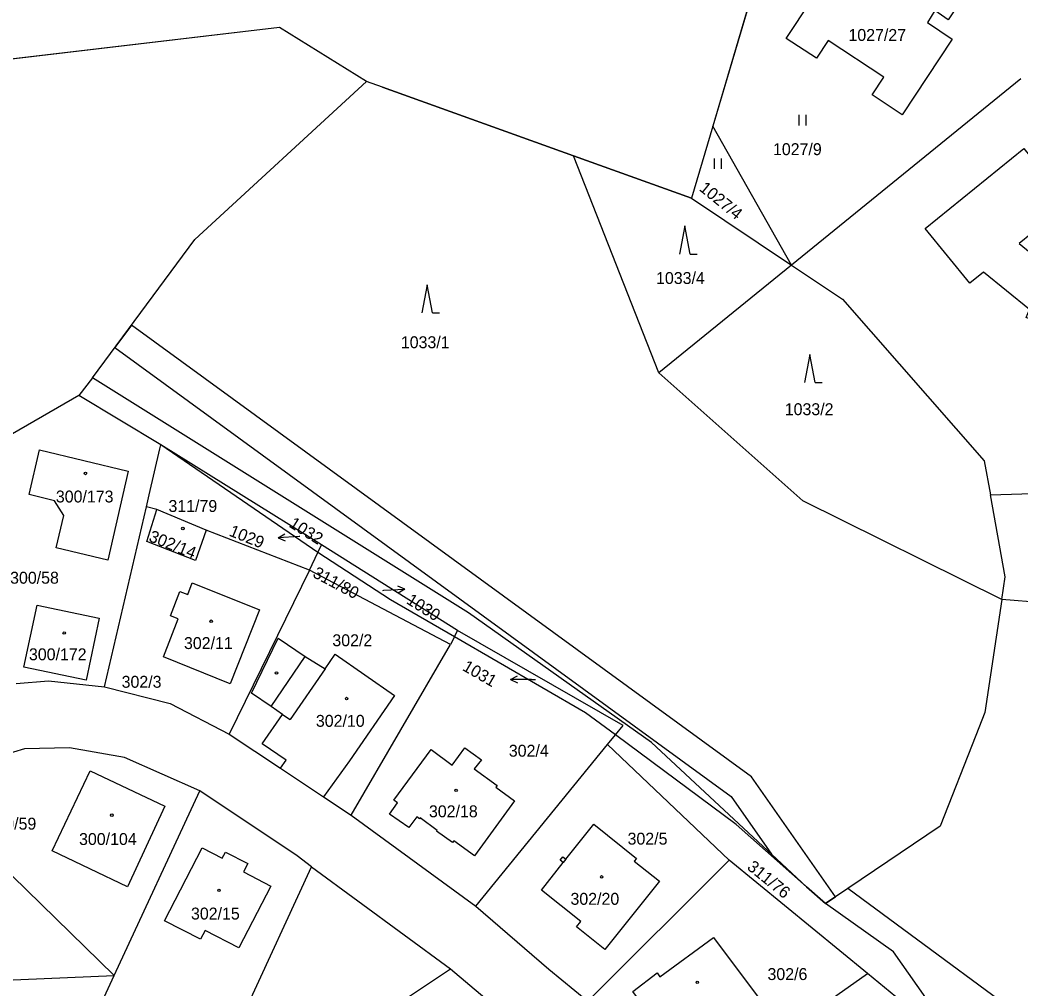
# Model space of a CAD drawing. Extents: x -757266 to -753360, y -1162585 to -1157740.
# Drawn here: x -754707.7 to -754565.1, y -1160582.8 to -1160444.8 of the extents above; entities that cross this region are included whole.
import ezdxf

# ---------------------------------------------------------------- set-up
doc = ezdxf.new("R2010")
doc.units = 0
for name, color, linetype in [('Hranice kat_území', 7, 'Continuous'), ('Hranice parcel', 7, 'Continuous'), ('Parcelní čísla', 7, 'Continuous'), ('Pop  PČ popisy', 7, 'Continuous'), ('Vnitřní kresba', 7, 'Continuous'), ('Věcná břemena k části', 7, 'Continuous'), ('Značky budov', 7, 'Continuous'), ('Značky kultur', 7, 'Continuous')]:
    doc.layers.add(name, color=color, linetype=linetype)

msp = doc.modelspace()

# ---------------------------------------------------------------- linework, layer by layer
at = {"layer": 'Hranice kat_území'}
msp.add_lwpolyline([(-754561.41, -1160428.29), (-754599.4, -1160427.7), (-754608.96, -1160459.95), (-754612, -1160470.2), (-754628.81, -1160464.16), (-754656.06, -1160454.38), (-754658.34, -1160453.56), (-754670.71, -1160445.87), (-754748.18, -1160454.98), (-754763.13, -1160445.62), (-754770.6, -1160434.89), (-754825.24, -1160422.53), (-754831.13, -1160423.76), (-754836.68, -1160424.92)], dxfattribs=at)
at = {"layer": 'Hranice parcel'}
for p, q in [((-754599.4, -1160427.7), (-754608.96, -1160459.95)), ((-754670.71, -1160445.87), (-754748.18, -1160454.98)), ((-754658.34, -1160453.56), (-754670.71, -1160445.87)), ((-754656.06, -1160454.38), (-754658.34, -1160453.56)), ((-754565.04, -1160453.21), (-754597.74, -1160479.74)), ((-754656.06, -1160454.38), (-754628.81, -1160464.16)), ((-754608.96, -1160459.95), (-754612, -1160470.2)), ((-754597.74, -1160479.74), (-754608.96, -1160459.95)), ((-754628.81, -1160464.16), (-754612, -1160470.2)), ((-754616.64, -1160495.12), (-754628.81, -1160464.16)), ((-754612, -1160470.2), (-754597.74, -1160479.74)), ((-754597.74, -1160479.74), (-754616.64, -1160495.12)), ((-754697.37, -1160495.81), (-754699.35, -1160498.35)), ((-754699.35, -1160498.35), (-754718.28, -1160509.25)), ((-754687.64, -1160505.4), (-754699.35, -1160498.35)), ((-754665.25, -1160520.72), (-754687.64, -1160505.4)), ((-754664.73, -1160519.64), (-754687.64, -1160505.4)), ((-754569.37, -1160512.49), (-754528.72, -1160511.17)), ((-754695.7, -1160539.88), (-754689.68, -1160514.2)), ((-754688.24, -1160514.59), (-754689.68, -1160514.2)), ((-754681.17, -1160517.53), (-754688.24, -1160514.59)), ((-754666.47, -1160523.27), (-754681.17, -1160517.53)), ((-754665.25, -1160520.72), (-754664.73, -1160519.64)), ((-754645.36, -1160531.87), (-754664.73, -1160519.64)), ((-754666.47, -1160523.27), (-754665.25, -1160520.72)), ((-754666.47, -1160523.27), (-754677.92, -1160546.62)), ((-754646.33, -1160533.85), (-754666.47, -1160523.27)), ((-754550.24, -1160528.86), (-754567.75, -1160527.45)), ((-754645.8, -1160532.77), (-754645.36, -1160531.87)), ((-754645.8, -1160532.77), (-754646.33, -1160533.85)), ((-754660.51, -1160558.19), (-754646.33, -1160533.85)), ((-754677.92, -1160546.62), (-754670.6, -1160551.49)), ((-754623.96, -1160548.12), (-754622.84, -1160546.75)), ((-754642.73, -1160571.16), (-754623.96, -1160548.12)), ((-754606.61, -1160564.59), (-754623.96, -1160548.12)), ((-754670.6, -1160551.49), (-754664.45, -1160555.57)), ((-754694.29, -1160581.04), (-754682.09, -1160554.71)), ((-754720.47, -1160555.5), (-754694.29, -1160581.04)), ((-754664.45, -1160555.57), (-754660.51, -1160558.19)), ((-754660.51, -1160558.19), (-754642.73, -1160571.16)), ((-754626.77, -1160584.73), (-754606.61, -1160564.59)), ((-754586.88, -1160580.76), (-754606.61, -1160564.59)), ((-754677.4, -1160589.9), (-754666.17, -1160565.55)), ((-754666.17, -1160565.55), (-754646.35, -1160580.1)), ((-754592.9, -1160570.8), (-754595.57, -1160568.42)), ((-754589.68, -1160568.64), (-754592.9, -1160570.8)), ((-754670.52, -1160596.18), (-754646.35, -1160580.1)), ((-754729.14, -1160582.6), (-754694.29, -1160581.04)), ((-754696.01, -1160584.78), (-754694.29, -1160581.04)), ((-754573.05, -1160592.1), (-754586.88, -1160580.76))]:
    msp.add_line(p, q, dxfattribs=at)
for points in [[(-754580.41, -1160431.85), (-754570.99, -1160438.07), (-754575.39, -1160444.75), (-754577.29, -1160443.45), (-754578.34, -1160445.15), (-754574.81, -1160447.52), (-754581.93, -1160458.3), (-754586.23, -1160455.47), (-754584.57, -1160452.94), (-754592.51, -1160447.73), (-754594.17, -1160450.25), (-754598.47, -1160447.42), (-754591.34, -1160436.64), (-754585.8, -1160440.24), (-754580.41, -1160431.85)], [(-754697.37, -1160495.81), (-754682.82, -1160476.1), (-754658.34, -1160453.56)], [(-754551.18, -1160493.01), (-754551.92, -1160494.72), (-754562.62, -1160489.98), (-754561.86, -1160488.29), (-754564.28, -1160487.21), (-754563.77, -1160486.1), (-754570.33, -1160480.78), (-754572.3, -1160482.34), (-754578.65, -1160474.52), (-754564.61, -1160463.11), (-754558.25, -1160470.95), (-754565.26, -1160476.67), (-754561.08, -1160480.09), (-754559.99, -1160477.51), (-754541.63, -1160485.62), (-754545.9, -1160495.32), (-754551.18, -1160493.01)], [(-754597.74, -1160479.74), (-754590.44, -1160484.62), (-754570.24, -1160507.65), (-754569.37, -1160512.49)], [(-754595.57, -1160568.42), (-754617.69, -1160547.83), (-754643.8, -1160529.32), (-754697.37, -1160495.81)], [(-754567.75, -1160527.45), (-754596.13, -1160513.36), (-754616.64, -1160495.12)], [(-754701.5, -1160515.46), (-754702.79, -1160513.35), (-754706.43, -1160512.48), (-754704.93, -1160506.11), (-754692.29, -1160509.15), (-754695.23, -1160521.83), (-754702.56, -1160520.07), (-754701.5, -1160515.46)], [(-754689.68, -1160514.2), (-754689.29, -1160512.5), (-754687.77, -1160505.95), (-754687.64, -1160505.4)], [(-754567.75, -1160527.45), (-754567.27, -1160524.22), (-754569.37, -1160512.49)], [(-754681.17, -1160517.53), (-754682.73, -1160521.87), (-754689.65, -1160519.16), (-754688.24, -1160514.59)], [(-754645.8, -1160532.77), (-754654.9, -1160527.5), (-754665.25, -1160520.72)], [(-754683.82, -1160526.7), (-754683.19, -1160525.08), (-754673.56, -1160528.91), (-754677.76, -1160539.46), (-754687.29, -1160535.63), (-754685.18, -1160530.21), (-754686.29, -1160529.77), (-754684.93, -1160526.27), (-754683.82, -1160526.7)], [(-754567.75, -1160527.45), (-754570.15, -1160543.54), (-754571.44, -1160546.84), (-754576.51, -1160559.77), (-754589.68, -1160568.64)], [(-754707.16, -1160537.08), (-754705.3, -1160528.23), (-754696.46, -1160530.11), (-754698.31, -1160538.96), (-754707.16, -1160537.08)], [(-754622.84, -1160546.75), (-754621.75, -1160545.41), (-754645.36, -1160531.87)], [(-754670.6, -1160551.49), (-754669.8, -1160550.34), (-754673.22, -1160548.02), (-754670.29, -1160543.82), (-754671.91, -1160542.71), (-754674.74, -1160540.77), (-754670.9, -1160532.95), (-754667.08, -1160535.57), (-754664.21, -1160537.3), (-754662.8, -1160535.24), (-754654.31, -1160541.11), (-754660.76, -1160550.44), (-754664.45, -1160555.57)], [(-754622.84, -1160546.75), (-754627.1, -1160543.6), (-754645.8, -1160532.77)], [(-754708.3, -1160539.4), (-754703.69, -1160539.02), (-754695.7, -1160539.88)], [(-754695.7, -1160539.88), (-754686.34, -1160542.25), (-754677.92, -1160546.62)], [(-754595.57, -1160568.42), (-754605.6, -1160559.5), (-754622.84, -1160546.75)], [(-754682.09, -1160554.71), (-754692.82, -1160549.97), (-754700.68, -1160548.61), (-754707.08, -1160548.74), (-754713.39, -1160550.62), (-754720.47, -1160555.5)], [(-754649.12, -1160548.84), (-754646.1, -1160551.05), (-754644.29, -1160548.58), (-754641.95, -1160550.29), (-754642.98, -1160551.59), (-754639.71, -1160553.95), (-754639.89, -1160554.19), (-754637.22, -1160556.13), (-754642.93, -1160564.01), (-754645.89, -1160561.86), (-754646.06, -1160562.1), (-754648.32, -1160560.48), (-754648.23, -1160560.36), (-754650.66, -1160558.59), (-754650.75, -1160558.72), (-754651.17, -1160558.41), (-754652.29, -1160559.96), (-754655.06, -1160558.03), (-754653.91, -1160556.44), (-754654.41, -1160556.07), (-754649.12, -1160548.84)], [(-754692.42, -1160568.43), (-754703.15, -1160563.29), (-754697.73, -1160551.88), (-754687.07, -1160556.9), (-754692.42, -1160568.43)], [(-754666.17, -1160565.55), (-754668.23, -1160564.01), (-754682.09, -1160554.71)], [(-754627.77, -1160573.33), (-754633.38, -1160568.87), (-754630.27, -1160564.95), (-754630.7, -1160564.61), (-754630.33, -1160564.14), (-754629.9, -1160564.48), (-754625.91, -1160559.47), (-754619.83, -1160564.35), (-754620.14, -1160564.74), (-754616.56, -1160567.61), (-754624.34, -1160577.34), (-754628.39, -1160574.12), (-754627.77, -1160573.33)], [(-754687.15, -1160573.26), (-754681.74, -1160562.85), (-754678.9, -1160564.34), (-754678.43, -1160563.45), (-754675.26, -1160565.1), (-754675.87, -1160566.29), (-754671.95, -1160568.32), (-754676.55, -1160577.1), (-754681.35, -1160574.65), (-754681.98, -1160575.86), (-754687.15, -1160573.26)], [(-754525.57, -1160600.85), (-754530.19, -1160600.86), (-754557.24, -1160592.58), (-754589.68, -1160568.64)], [(-754642.73, -1160571.16), (-754632.34, -1160580.17), (-754626.77, -1160584.73)], [(-754573.05, -1160592.1), (-754583.17, -1160577.68), (-754592.9, -1160570.8)], [(-754608.87, -1160575.61), (-754602.05, -1160584.69), (-754606.25, -1160587.9), (-754607.41, -1160586.32), (-754614.29, -1160591.54), (-754620.36, -1160583.31), (-754616.9, -1160580.69), (-754616.48, -1160581.25), (-754608.87, -1160575.61)], [(-754646.35, -1160580.1), (-754633.8, -1160590.71), (-754632.57, -1160592.31)], [(-754614.24, -1160600.29), (-754591.25, -1160583.88), (-754586.88, -1160580.76)]]:
    msp.add_lwpolyline(points, dxfattribs=at)
at = {"layer": 'Pop  PČ popisy'}
for p, q in [((-754670.937, -1160518.617), (-754669.963, -1160518.065)), ((-754667.94, -1160518.46), (-754670.937, -1160518.617)), ((-754670.937, -1160518.617), (-754669.911, -1160519.065)), ((-754667.84, -1160518.45), (-754667.94, -1160518.46)), ((-754656, -1160526.13), (-754655.84, -1160526.12)), ((-754655.84, -1160526.12), (-754652.843, -1160525.963)), ((-754652.843, -1160525.963), (-754653.869, -1160525.515)), ((-754652.843, -1160525.963), (-754653.817, -1160526.515)), ((-754637.811, -1160538.84), (-754636.81, -1160538.339)), ((-754634.81, -1160538.84), (-754637.811, -1160538.84)), ((-754637.811, -1160538.84), (-754636.81, -1160539.341)), ((-754634.81, -1160538.84), (-754634.22, -1160538.84))]:
    msp.add_line(p, q, dxfattribs=at)
at = {"layer": 'Vnitřní kresba'}
for p, q in [((-754671.91, -1160542.71), (-754667.08, -1160535.57)), ((-754664.21, -1160537.3), (-754669.2, -1160544.57)), ((-754670.29, -1160543.82), (-754669.2, -1160544.57)), ((-754629.9, -1160564.48), (-754630.27, -1160564.95))]:
    msp.add_line(p, q, dxfattribs=at)
at = {"layer": 'Věcná břemena k části'}
msp.add_lwpolyline([(-754691.82, -1160488.3), (-754694.2, -1160491.51), (-754606.33, -1160555.55), (-754600.57, -1160563.77), (-754595.57, -1160568.42), (-754592.9, -1160570.8), (-754591.44, -1160569.82), (-754603.43, -1160552.71)], close=True, dxfattribs=at)
at = {"layer": 'Značky budov'}
for centre in [(-754698.3968, -1160509.4592), (-754684.5068, -1160517.3092), (-754680.4768, -1160530.5292), (-754701.4268, -1160532.1992), (-754671.1568, -1160537.9092), (-754661.1568, -1160541.5592), (-754645.5468, -1160554.6392), (-754694.6368, -1160558.1892), (-754624.7968, -1160566.9892), (-754679.3668, -1160568.9192), (-754611.1568, -1160582.0392)]:
    msp.add_circle(centre, 0.175, dxfattribs=at)
at = {"layer": 'Značky kultur'}
for p, q in [((-754596.631, -1160459.84), (-754596.631, -1160458.34)), ((-754595.63, -1160459.84), (-754595.63, -1160458.34)), ((-754608.691, -1160466.04), (-754608.691, -1160464.54)), ((-754607.69, -1160466.04), (-754607.69, -1160464.54)), ((-754612.93, -1160474.17), (-754613.68, -1160478.17)), ((-754612.18, -1160478.17), (-754612.93, -1160474.17)), ((-754612.18, -1160478.17), (-754611.184, -1160478.17)), ((-754649.68, -1160482.55), (-754650.43, -1160486.55)), ((-754648.93, -1160486.55), (-754649.68, -1160482.55)), ((-754648.93, -1160486.55), (-754647.934, -1160486.55)), ((-754595.12, -1160492.48), (-754595.87, -1160496.48)), ((-754594.37, -1160496.48), (-754595.12, -1160492.48)), ((-754594.37, -1160496.48), (-754593.374, -1160496.48))]:
    msp.add_line(p, q, dxfattribs=at)

# ---------------------------------------------------------------- texts
at = {"layer": 'Parcelní čísla'}
for s, p in [('1027/27', (-754589.606, -1160447.78)), ('1027/9', (-754600.367, -1160464.07)), ('1033/4', (-754617.037, -1160482.44)), ('1033/1', (-754653.427, -1160491.6)), ('1033/2', (-754598.687, -1160501.15)), ('300/173', (-754702.616, -1160513.6)), ('311/79', (-754686.56, -1160514.95)), ('300/58', (-754709.14, -1160525.18)), ('302/11', (-754684.35, -1160534.5)), ('302/2', (-754663.19, -1160534.1)), ('300/172', (-754706.456, -1160536.1)), ('302/3', (-754693.24, -1160540.02)), ('302/10', (-754665.54, -1160545.59)), ('302/4', (-754638.03, -1160549.85)), ('302/18', (-754649.42, -1160558.49)), ('300/59', (-754712.36, -1160560.25)), ('302/5', (-754621.1, -1160562.39)), ('300/104', (-754699.31, -1160562.44)), ('302/20', (-754629.24, -1160570.97)), ('302/15', (-754683.35, -1160573.07)), ('302/6', (-754601.15, -1160581.7))]:
    msp.add_text(s, height=1.7, dxfattribs=at).set_placement(p)
for s, rotation, p in [('1027/4', 321, (-754611.002, -1160469.016)), ('1032', 328, (-754669.5, -1160517)), ('302/14', 338, (-754689.488, -1160519.068)), ('1029', 338, (-754678.033, -1160518.299)), ('311/80', 332, (-754666.119, -1160524.16)), ('1030', 328, (-754652.769, -1160527.915)), ('1031', 329.999997, (-754644.776, -1160537.451)), ('311/76', 321, (-754604.174, -1160565.81))]:
    msp.add_text(s, height=1.7, rotation=rotation, dxfattribs=at).set_placement(p)

doc.saveas('drawing.dxf')
